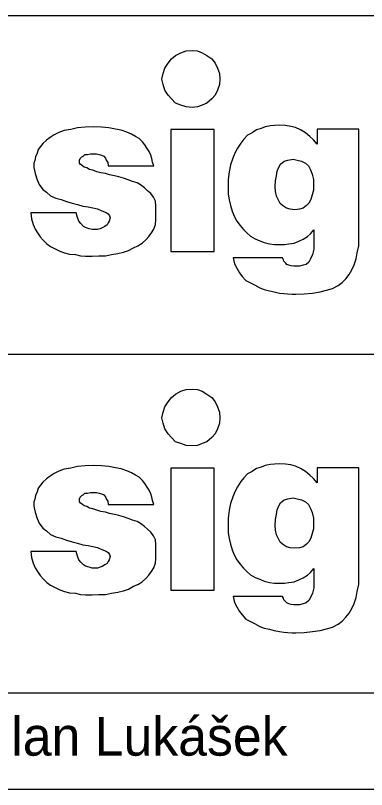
# Model space of a CAD drawing. Extents: x -172 to -151, y 333 to 362.7.
# Drawn here: x -158.675 to -156.861, y 343 to 347 of the extents above; entities that cross this region are included whole.
import ezdxf

# ---------------------------------------------------------------- set-up
doc = ezdxf.new("R2010")
doc.units = 0
for name, color, linetype in [('Info o rozpiskách', 7, 'Continuous'), ('popis', 7, 'Continuous'), ('Rozpiska_pole_6', 7, 'Continuous')]:
    doc.layers.add(name, color=color, linetype=linetype)

msp = doc.modelspace()

# ---------------------------------------------------------------- linework, layer by layer
at = {"layer": 'Info o rozpiskách'}
for points in [[(-157.7618, 346.8197), (-157.7338, 346.8178), (-157.7097, 346.8078), (-157.6857, 346.7937), (-157.6597, 346.7757), (-157.6437, 346.7537), (-157.6316, 346.7276), (-157.6216, 346.6996), (-157.6196, 346.6715), (-157.6216, 346.6435), (-157.6316, 346.6134), (-157.6437, 346.5874), (-157.6597, 346.5694), (-157.6857, 346.5473), (-157.7097, 346.5373), (-157.7338, 346.5273), (-157.7618, 346.5253), (-157.7939, 346.5273), (-157.8199, 346.5373), (-157.848, 346.5473), (-157.868, 346.5694), (-157.886, 346.5874), (-157.9041, 346.6134), (-157.9121, 346.6435), (-157.9181, 346.6715), (-157.9121, 346.6996), (-157.9041, 346.7276), (-157.886, 346.7537), (-157.868, 346.7757), (-157.848, 346.7937), (-157.8199, 346.8078), (-157.7939, 346.8178), (-157.7618, 346.8197)], [(-157.7618, 345.0697), (-157.7338, 345.0678), (-157.7097, 345.0578), (-157.6857, 345.0437), (-157.6597, 345.0257), (-157.6437, 345.0037), (-157.6316, 344.9776), (-157.6216, 344.9496), (-157.6196, 344.9215), (-157.6216, 344.8935), (-157.6316, 344.8634), (-157.6437, 344.8374), (-157.6597, 344.8194), (-157.6857, 344.7973), (-157.7097, 344.7873), (-157.7338, 344.7773), (-157.7618, 344.7753), (-157.7939, 344.7773), (-157.8199, 344.7873), (-157.848, 344.7973), (-157.868, 344.8194), (-157.886, 344.8374), (-157.9041, 344.8634), (-157.9121, 344.8935), (-157.9181, 344.9215), (-157.9121, 344.9496), (-157.9041, 344.9776), (-157.886, 345.0037), (-157.868, 345.0257), (-157.848, 345.0437), (-157.8199, 345.0578), (-157.7939, 345.0678), (-157.7618, 345.0697)]]:
    msp.add_lwpolyline(points, dxfattribs=at)
at = {"layer": 'popis'}
for points in [[(-158.1966, 346.2228), (-157.9602, 346.2228), (-157.9662, 346.2428), (-157.9702, 346.2609), (-157.9762, 346.2788), (-157.9842, 346.2969), (-157.9943, 346.3129), (-158.0062, 346.331), (-158.0182, 346.347), (-158.0363, 346.365), (-158.0543, 346.375), (-158.0763, 346.3871), (-158.1004, 346.3971), (-158.1284, 346.4071), (-158.1585, 346.4131), (-158.1925, 346.4191), (-158.2306, 346.4231), (-158.2726, 346.4251), (-158.3147, 346.4231), (-158.3548, 346.4191), (-158.3888, 346.4111), (-158.4229, 346.4051), (-158.451, 346.3951), (-158.475, 346.3831), (-158.495, 346.369), (-158.5151, 346.355), (-158.5331, 346.339), (-158.5451, 346.3229), (-158.5572, 346.3069), (-158.5631, 346.2889), (-158.5712, 346.2688), (-158.5751, 346.2509), (-158.5792, 346.2368), (-158.5792, 346.2147), (-158.5732, 346.1827), (-158.5631, 346.1507), (-158.5531, 346.1266), (-158.5331, 346.1006), (-158.5151, 346.0866), (-158.4931, 346.0685), (-158.467, 346.0565), (-158.439, 346.0485), (-158.4109, 346.0385), (-158.3828, 346.0305), (-158.3548, 346.0225), (-158.3268, 346.0144), (-158.2987, 346.0105), (-158.2747, 346.0065), (-158.2506, 346.0004), (-158.2286, 345.9904), (-158.2066, 345.9824), (-158.1966, 345.9744), (-158.1885, 345.9644), (-158.1865, 345.9544), (-158.1906, 345.9363), (-158.1966, 345.9283), (-158.2006, 345.9183), (-158.2126, 345.9103), (-158.2266, 345.9022), (-158.2366, 345.8983), (-158.2506, 345.8943), (-158.2647, 345.8943), (-158.2787, 345.8943), (-158.2947, 345.8983), (-158.3128, 345.9043), (-158.3228, 345.9103), (-158.3368, 345.9243), (-158.3468, 345.9363), (-158.3548, 345.9563), (-158.3608, 345.9804), (-158.5952, 345.9804), (-158.5912, 345.9484), (-158.5832, 345.9203), (-158.5732, 345.8962), (-158.5612, 345.8762), (-158.5471, 345.8562), (-158.5311, 345.8381), (-158.5131, 345.8202), (-158.4931, 345.8061), (-158.469, 345.7941), (-158.445, 345.7821), (-158.4209, 345.7741), (-158.3949, 345.7661), (-158.3648, 345.764), (-158.3388, 345.758), (-158.3128, 345.756), (-158.2787, 345.756), (-158.2446, 345.758), (-158.2106, 345.758), (-158.1785, 345.764), (-158.1465, 345.77), (-158.1165, 345.7761), (-158.0904, 345.7861), (-158.0643, 345.8001), (-158.0423, 345.8102), (-158.0203, 345.8241), (-158.0002, 345.8422), (-157.9862, 345.8582), (-157.9722, 345.8762), (-157.9602, 345.8962), (-157.9522, 345.9203), (-157.9501, 345.9443), (-157.9501, 345.9684), (-157.9501, 345.9744), (-157.9501, 345.9804), (-157.9501, 345.9864), (-157.9501, 345.9924), (-157.9501, 346.0004), (-157.9501, 346.0065), (-157.9501, 346.0105), (-157.9501, 346.0144), (-157.9522, 346.0405), (-157.9622, 346.0605), (-157.9762, 346.0806), (-157.9922, 346.0946), (-158.0082, 346.1086), (-158.0282, 346.1246), (-158.0463, 346.1347), (-158.0703, 346.1427), (-158.0924, 346.1507), (-158.1165, 346.1587), (-158.1404, 346.1667), (-158.1625, 346.1707), (-158.1885, 346.1767), (-158.2106, 346.1827), (-158.2346, 346.1868), (-158.2547, 346.1928), (-158.2747, 346.2007), (-158.2927, 346.2047), (-158.3067, 346.2128), (-158.3207, 346.2168), (-158.3288, 346.2228), (-158.3407, 346.2308), (-158.3448, 346.2368), (-158.3448, 346.2448), (-158.3448, 346.2528), (-158.3407, 346.2609), (-158.3328, 346.2688), (-158.3247, 346.2729), (-158.3168, 346.2809), (-158.3027, 346.2809), (-158.2867, 346.2849), (-158.2726, 346.2849), (-158.2566, 346.2849), (-158.2426, 346.2809), (-158.2306, 346.2788), (-158.2186, 346.2729), (-158.2106, 346.2628), (-158.2066, 346.2528), (-158.1985, 346.2408), (-158.1966, 346.2228)], [(-157.872, 346.4111), (-157.872, 345.78), (-157.6477, 345.78), (-157.6477, 346.4111), (-157.872, 346.4111)], [(-157.1168, 346.4131), (-157.1168, 346.335), (-157.1349, 346.357), (-157.1549, 346.375), (-157.1769, 346.3931), (-157.203, 346.4091), (-157.229, 346.4211), (-157.253, 346.4271), (-157.2791, 346.4312), (-157.3091, 346.4331), (-157.3372, 346.4312), (-157.3572, 346.4291), (-157.3852, 346.4251), (-157.4053, 346.4151), (-157.4293, 346.4091), (-157.4513, 346.3931), (-157.4754, 346.381), (-157.4954, 346.361), (-157.5115, 346.341), (-157.5275, 346.315), (-157.5415, 346.2889), (-157.5515, 346.2628), (-157.5635, 346.2288), (-157.5715, 346.1928), (-157.5756, 346.1527), (-157.5756, 346.1106), (-157.5756, 346.0765), (-157.5715, 346.0465), (-157.5635, 346.0184), (-157.5555, 345.9884), (-157.5455, 345.9624), (-157.5315, 345.9363), (-157.5134, 345.9143), (-157.4974, 345.8943), (-157.4794, 345.8762), (-157.4613, 345.8602), (-157.4374, 345.8462), (-157.4133, 345.8362), (-157.3893, 345.8262), (-157.3632, 345.8202), (-157.3372, 345.8161), (-157.3091, 345.8161), (-157.285, 345.8161), (-157.263, 345.8202), (-157.235, 345.8241), (-157.2109, 345.8341), (-157.1889, 345.8441), (-157.1669, 345.8582), (-157.1509, 345.8722), (-157.1328, 345.8922), (-157.1328, 345.8341), (-157.1328, 345.7921), (-157.1409, 345.764), (-157.1509, 345.742), (-157.1589, 345.726), (-157.1729, 345.714), (-157.1889, 345.71), (-157.2069, 345.704), (-157.2269, 345.704), (-157.237, 345.704), (-157.251, 345.7059), (-157.263, 345.71), (-157.2731, 345.714), (-157.2791, 345.7219), (-157.2891, 345.73), (-157.2911, 345.738), (-157.2951, 345.748), (-157.5495, 345.748), (-157.5435, 345.7159), (-157.5315, 345.694), (-157.5175, 345.6699), (-157.5034, 345.6519), (-157.4854, 345.6299), (-157.4613, 345.6178), (-157.4393, 345.6078), (-157.4133, 345.5918), (-157.3893, 345.5837), (-157.3632, 345.5778), (-157.3391, 345.5718), (-157.3111, 345.5658), (-157.2891, 345.5637), (-157.269, 345.5617), (-157.245, 345.5597), (-157.2269, 345.5597), (-157.1829, 345.5617), (-157.1409, 345.5658), (-157.1008, 345.5718), (-157.0687, 345.5797), (-157.0367, 345.5897), (-157.0086, 345.6038), (-156.9866, 345.6198), (-156.9686, 345.6399), (-156.9505, 345.6619), (-156.9365, 345.6859), (-156.9245, 345.7119), (-156.9145, 345.742), (-156.9105, 345.7741), (-156.9005, 345.8102), (-156.9005, 345.8482), (-156.9005, 345.8922), (-156.9005, 346.4131), (-157.1168, 346.4131)], [(-157.241, 346.2568), (-157.219, 346.2528), (-157.1969, 346.2468), (-157.1769, 346.2368), (-157.1609, 346.2228), (-157.1509, 346.2028), (-157.1428, 346.1807), (-157.1349, 346.1527), (-157.1349, 346.1226), (-157.1349, 346.0966), (-157.1428, 346.0725), (-157.1488, 346.0485), (-157.1589, 346.0305), (-157.1709, 346.0184), (-157.1889, 346.0044), (-157.2069, 345.9984), (-157.231, 345.9965), (-157.255, 345.9984), (-157.275, 346.0044), (-157.2951, 346.0184), (-157.3071, 346.0285), (-157.3171, 346.0485), (-157.3271, 346.0665), (-157.3312, 346.0906), (-157.3331, 346.1166), (-157.3312, 346.1447), (-157.3271, 346.1707), (-157.3231, 346.1947), (-157.3152, 346.2168), (-157.3051, 346.2308), (-157.2871, 346.2468), (-157.2671, 346.2528), (-157.241, 346.2568)], [(-157.1168, 344.6631), (-157.1168, 344.585), (-157.1349, 344.607), (-157.1549, 344.625), (-157.1769, 344.6431), (-157.203, 344.6591), (-157.229, 344.6711), (-157.253, 344.6771), (-157.2791, 344.6812), (-157.3091, 344.6831), (-157.3372, 344.6812), (-157.3572, 344.6791), (-157.3852, 344.6751), (-157.4053, 344.6651), (-157.4293, 344.6591), (-157.4513, 344.6431), (-157.4754, 344.631), (-157.4954, 344.611), (-157.5115, 344.591), (-157.5275, 344.565), (-157.5415, 344.5389), (-157.5515, 344.5128), (-157.5635, 344.4788), (-157.5715, 344.4428), (-157.5756, 344.4027), (-157.5756, 344.3606), (-157.5756, 344.3265), (-157.5715, 344.2965), (-157.5635, 344.2684), (-157.5555, 344.2384), (-157.5455, 344.2124), (-157.5315, 344.1863), (-157.5134, 344.1643), (-157.4974, 344.1443), (-157.4794, 344.1262), (-157.4613, 344.1102), (-157.4374, 344.0962), (-157.4133, 344.0862), (-157.3893, 344.0762), (-157.3632, 344.0702), (-157.3372, 344.0661), (-157.3091, 344.0661), (-157.285, 344.0661), (-157.263, 344.0702), (-157.235, 344.0741), (-157.2109, 344.0841), (-157.1889, 344.0941), (-157.1669, 344.1082), (-157.1509, 344.1222), (-157.1328, 344.1422), (-157.1328, 344.0841), (-157.1328, 344.0421), (-157.1409, 344.014), (-157.1509, 343.992), (-157.1589, 343.976), (-157.1729, 343.964), (-157.1889, 343.96), (-157.2069, 343.954), (-157.2269, 343.954), (-157.237, 343.954), (-157.251, 343.9559), (-157.263, 343.96), (-157.2731, 343.964), (-157.2791, 343.9719), (-157.2891, 343.98), (-157.2911, 343.988), (-157.2951, 343.998), (-157.5495, 343.998), (-157.5435, 343.9659), (-157.5315, 343.944), (-157.5175, 343.9199), (-157.5034, 343.9019), (-157.4854, 343.8799), (-157.4613, 343.8678), (-157.4393, 343.8578), (-157.4133, 343.8418), (-157.3893, 343.8337), (-157.3632, 343.8278), (-157.3391, 343.8218), (-157.3111, 343.8158), (-157.2891, 343.8137), (-157.269, 343.8117), (-157.245, 343.8097), (-157.2269, 343.8097), (-157.1829, 343.8117), (-157.1409, 343.8158), (-157.1008, 343.8218), (-157.0687, 343.8297), (-157.0367, 343.8397), (-157.0086, 343.8538), (-156.9866, 343.8698), (-156.9686, 343.8899), (-156.9505, 343.9119), (-156.9365, 343.9359), (-156.9245, 343.9619), (-156.9145, 343.992), (-156.9105, 344.0241), (-156.9005, 344.0602), (-156.9005, 344.0982), (-156.9005, 344.1422), (-156.9005, 344.6631), (-157.1168, 344.6631)], [(-158.1966, 344.4728), (-157.9602, 344.4728), (-157.9662, 344.4928), (-157.9702, 344.5109), (-157.9762, 344.5288), (-157.9842, 344.5469), (-157.9943, 344.5629), (-158.0062, 344.581), (-158.0182, 344.597), (-158.0363, 344.615), (-158.0543, 344.625), (-158.0763, 344.6371), (-158.1004, 344.6471), (-158.1284, 344.6571), (-158.1585, 344.6631), (-158.1925, 344.6691), (-158.2306, 344.6731), (-158.2726, 344.6751), (-158.3147, 344.6731), (-158.3548, 344.6691), (-158.3888, 344.6611), (-158.4229, 344.6551), (-158.451, 344.6451), (-158.475, 344.6331), (-158.495, 344.619), (-158.5151, 344.605), (-158.5331, 344.589), (-158.5451, 344.5729), (-158.5572, 344.5569), (-158.5631, 344.5389), (-158.5712, 344.5188), (-158.5751, 344.5009), (-158.5792, 344.4868), (-158.5792, 344.4647), (-158.5732, 344.4327), (-158.5631, 344.4007), (-158.5531, 344.3766), (-158.5331, 344.3506), (-158.5151, 344.3366), (-158.4931, 344.3185), (-158.467, 344.3065), (-158.439, 344.2985), (-158.4109, 344.2885), (-158.3828, 344.2805), (-158.3548, 344.2725), (-158.3268, 344.2644), (-158.2987, 344.2605), (-158.2747, 344.2565), (-158.2506, 344.2504), (-158.2286, 344.2404), (-158.2066, 344.2324), (-158.1966, 344.2244), (-158.1885, 344.2144), (-158.1865, 344.2044), (-158.1906, 344.1863), (-158.1966, 344.1783), (-158.2006, 344.1683), (-158.2126, 344.1603), (-158.2266, 344.1522), (-158.2366, 344.1483), (-158.2506, 344.1443), (-158.2647, 344.1443), (-158.2787, 344.1443), (-158.2947, 344.1483), (-158.3128, 344.1543), (-158.3228, 344.1603), (-158.3368, 344.1743), (-158.3468, 344.1863), (-158.3548, 344.2063), (-158.3608, 344.2304), (-158.5952, 344.2304), (-158.5912, 344.1984), (-158.5832, 344.1703), (-158.5732, 344.1462), (-158.5612, 344.1262), (-158.5471, 344.1062), (-158.5311, 344.0881), (-158.5131, 344.0702), (-158.4931, 344.0561), (-158.469, 344.0441), (-158.445, 344.0321), (-158.4209, 344.0241), (-158.3949, 344.0161), (-158.3648, 344.014), (-158.3388, 344.008), (-158.3128, 344.006), (-158.2787, 344.006), (-158.2446, 344.008), (-158.2106, 344.008), (-158.1785, 344.014), (-158.1465, 344.02), (-158.1165, 344.0261), (-158.0904, 344.0361), (-158.0643, 344.0501), (-158.0423, 344.0602), (-158.0203, 344.0741), (-158.0002, 344.0922), (-157.9862, 344.1082), (-157.9722, 344.1262), (-157.9602, 344.1462), (-157.9522, 344.1703), (-157.9501, 344.1943), (-157.9501, 344.2184), (-157.9501, 344.2244), (-157.9501, 344.2304), (-157.9501, 344.2364), (-157.9501, 344.2424), (-157.9501, 344.2504), (-157.9501, 344.2565), (-157.9501, 344.2605), (-157.9501, 344.2644), (-157.9522, 344.2905), (-157.9622, 344.3105), (-157.9762, 344.3306), (-157.9922, 344.3446), (-158.0082, 344.3586), (-158.0282, 344.3746), (-158.0463, 344.3847), (-158.0703, 344.3927), (-158.0924, 344.4007), (-158.1165, 344.4087), (-158.1404, 344.4167), (-158.1625, 344.4207), (-158.1885, 344.4267), (-158.2106, 344.4327), (-158.2346, 344.4368), (-158.2547, 344.4428), (-158.2747, 344.4507), (-158.2927, 344.4547), (-158.3067, 344.4628), (-158.3207, 344.4668), (-158.3288, 344.4728), (-158.3407, 344.4808), (-158.3448, 344.4868), (-158.3448, 344.4948), (-158.3448, 344.5028), (-158.3407, 344.5109), (-158.3328, 344.5188), (-158.3247, 344.5229), (-158.3168, 344.5309), (-158.3027, 344.5309), (-158.2867, 344.5349), (-158.2726, 344.5349), (-158.2566, 344.5349), (-158.2426, 344.5309), (-158.2306, 344.5288), (-158.2186, 344.5229), (-158.2106, 344.5128), (-158.2066, 344.5028), (-158.1985, 344.4908), (-158.1966, 344.4728)], [(-157.872, 344.6611), (-157.872, 344.03), (-157.6477, 344.03), (-157.6477, 344.6611), (-157.872, 344.6611)], [(-157.241, 344.5068), (-157.219, 344.5028), (-157.1969, 344.4968), (-157.1769, 344.4868), (-157.1609, 344.4728), (-157.1509, 344.4528), (-157.1428, 344.4307), (-157.1349, 344.4027), (-157.1349, 344.3726), (-157.1349, 344.3466), (-157.1428, 344.3225), (-157.1488, 344.2985), (-157.1589, 344.2805), (-157.1709, 344.2684), (-157.1889, 344.2544), (-157.2069, 344.2484), (-157.231, 344.2465), (-157.255, 344.2484), (-157.275, 344.2544), (-157.2951, 344.2684), (-157.3071, 344.2785), (-157.3171, 344.2985), (-157.3271, 344.3165), (-157.3312, 344.3406), (-157.3331, 344.3666), (-157.3312, 344.3947), (-157.3271, 344.4207), (-157.3231, 344.4447), (-157.3152, 344.4668), (-157.3051, 344.4808), (-157.2871, 344.4968), (-157.2671, 344.5028), (-157.241, 344.5068)]]:
    msp.add_lwpolyline(points, dxfattribs=at)
at = {"layer": 'Rozpiska_pole_6'}
for p, q in [((-170, 345.25), (-153, 345.25)), ((-170, 343.5), (-153, 343.5))]:
    msp.add_line(p, q, dxfattribs=at)
msp.add_lwpolyline([(-170, 347), (-153, 347), (-153, 343), (-170, 343)], close=True, dxfattribs=at)

# ---------------------------------------------------------------- texts
msp.add_text('Ing. Milan Lukášek', height=0.2, dxfattribs=at).set_placement((-159.4991, 343.175))

doc.saveas('drawing.dxf')
